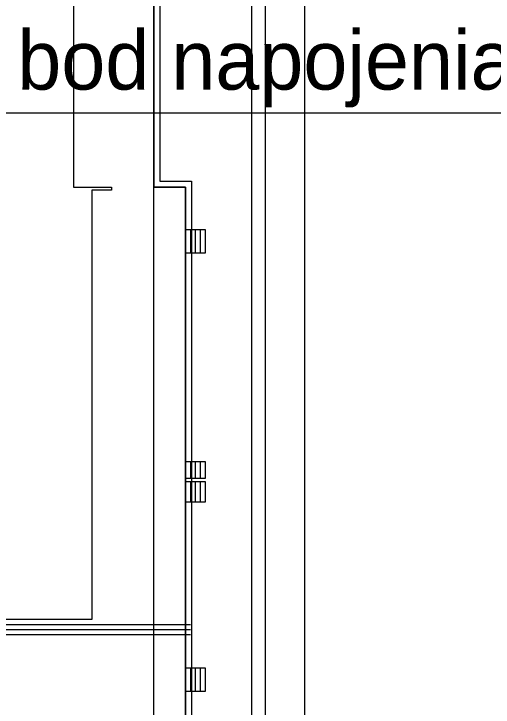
# Model space of a CAD drawing. Extents: x -263995 to -263575, y -1242437 to -1242140.
# Drawn here: x -263900.72 to -263876.42, y -1242207.77 to -1242172.65 of the extents above; entities that cross this region are included whole.
import ezdxf

# ---------------------------------------------------------------- set-up
doc = ezdxf.new("R2010")
doc.units = 0
doc.layers.add('KFA_2D_SITUACIA_DSP', color=7, linetype='Continuous')
doc.layers.add('POPIS', color=7, linetype='Continuous')

msp = doc.modelspace()

# ---------------------------------------------------------------- linework, layer by layer
at = {"layer": 'KFA_2D_SITUACIA_DSP'}
for p, q in [((-263887.968, -1242220.33), (-263887.968, -1242140.046)), ((-263885.968, -1242216.882), (-263885.968, -1242140.046)), ((-263893.618, -1242181.432), (-263893.618, -1242147.332)), ((-263888.673, -1242164.687), (-263888.673, -1242220.396)), ((-263893.318, -1242166.082), (-263893.318, -1242181.132)), ((-263893.618, -1242210.482), (-263893.618, -1242166.382)), ((-263893.618, -1242166.382), (-263893.618, -1242181.432)), ((-263897.693, -1242168.582), (-263897.693, -1242181.432)), ((-263893.318, -1242181.132), (-263891.718, -1242181.132)), ((-263891.718, -1242181.132), (-263891.718, -1242220.206)), ((-263897.693, -1242181.432), (-263895.768, -1242181.432)), ((-263895.768, -1242181.582), (-263896.768, -1242181.582)), ((-263896.768, -1242181.582), (-263896.768, -1242203.332)), ((-263895.768, -1242181.432), (-263895.768, -1242181.582)), ((-263892.018, -1242181.432), (-263893.618, -1242181.432)), ((-263893.618, -1242181.432), (-263892.018, -1242181.432)), ((-263892.018, -1242220.33), (-263892.018, -1242181.432)), ((-263892.018, -1242181.432), (-263892.018, -1242220.33)), ((-263892.018, -1242183.583), (-263891.018, -1242183.583)), ((-263891.768, -1242183.583), (-263891.768, -1242184.781)), ((-263891.518, -1242183.583), (-263891.518, -1242184.781)), ((-263891.268, -1242183.583), (-263891.268, -1242184.781)), ((-263891.018, -1242183.583), (-263891.018, -1242184.781)), ((-263891.018, -1242184.781), (-263892.018, -1242184.781)), ((-263892.018, -1242195.333), (-263891.018, -1242195.333)), ((-263891.768, -1242195.333), (-263891.768, -1242196.181)), ((-263891.518, -1242195.333), (-263891.518, -1242196.181)), ((-263891.268, -1242195.333), (-263891.268, -1242196.181)), ((-263891.018, -1242195.333), (-263891.018, -1242196.181)), ((-263891.018, -1242196.181), (-263892.018, -1242196.181)), ((-263892.018, -1242196.333), (-263891.018, -1242196.333)), ((-263891.768, -1242196.333), (-263891.768, -1242197.381)), ((-263891.518, -1242196.333), (-263891.518, -1242197.381)), ((-263891.268, -1242196.333), (-263891.268, -1242197.381)), ((-263891.018, -1242196.333), (-263891.018, -1242197.381)), ((-263891.018, -1242197.381), (-263892.018, -1242197.381)), ((-263896.768, -1242203.332), (-263909.118, -1242203.332)), ((-263910.108, -1242203.832), (-263891.768, -1242203.832)), ((-263910.004, -1242203.582), (-263891.768, -1242203.582)), ((-263910.211, -1242204.082), (-263891.768, -1242204.082)), ((-263892.018, -1242205.783), (-263891.018, -1242205.783)), ((-263891.768, -1242205.783), (-263891.768, -1242206.981)), ((-263891.518, -1242205.783), (-263891.518, -1242206.981)), ((-263891.268, -1242205.783), (-263891.268, -1242206.981)), ((-263891.018, -1242205.783), (-263891.018, -1242206.981)), ((-263891.018, -1242206.981), (-263892.018, -1242206.981))]:
    msp.add_line(p, q, dxfattribs=at)
at = {"layer": 'POPIS'}
msp.add_line((-263901.149, -1242177.668), (-263853.401, -1242177.668), dxfattribs=at)

# ---------------------------------------------------------------- texts
msp.add_text('bod napojenia do budovy', height=3, dxfattribs=at).set_placement((-263900.544, -1242176.489))

doc.saveas('drawing.dxf')
